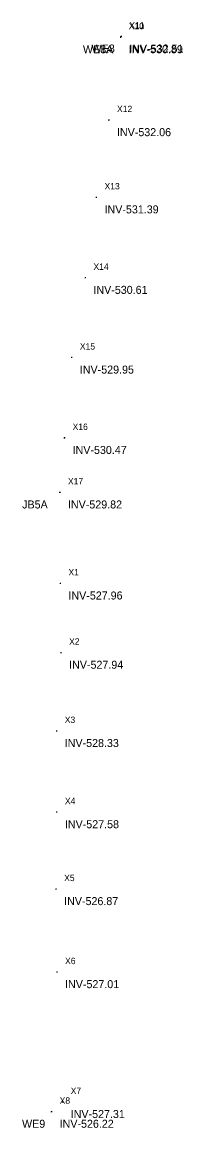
# Model space of a CAD drawing. Extents: x 1725597 to 1725698, y 658797 to 659487.
import ezdxf

# ---------------------------------------------------------------- set-up
doc = ezdxf.new("R2010")
doc.units = 0
for name, color, linetype in [('SURVEY - DRAINAGE - Storm Sewer - Points - Elevations', 7, 'Continuous'), ('SURVEY - DRAINAGE - Storm Sewer - Points - Locators', 7, 'Continuous'), ('SURVEY - DRAINAGE - Storm Sewer - Points - Numbers', 7, 'Continuous'), ('SURVEY - DRAINAGE - Storm Sewer Text', 7, 'Continuous')]:
    doc.layers.add(name, color=color, linetype=linetype)

msp = doc.modelspace()

# ---------------------------------------------------------------- linework, layer by layer
at = {"layer": 'SURVEY - DRAINAGE - Storm Sewer - Points - Locators'}
for p, q in [((1725659.05, 659477.75), (1725658.55, 659477.75)), ((1725658.8, 659477.5), (1725658.8, 659478)), ((1725658.8, 659477.75), (1725658.8, 659477.75)), ((1725658.8, 659477.75), (1725658.8, 659477.75)), ((1725659.43, 659478.22), (1725658.93, 659478.22)), ((1725659.18, 659477.97), (1725659.18, 659478.47)), ((1725659.18, 659478.22), (1725659.18, 659478.22)), ((1725659.18, 659478.22), (1725659.18, 659478.22)), ((1725651.71, 659425.98), (1725651.21, 659425.98)), ((1725651.46, 659425.73), (1725651.46, 659426.23)), ((1725651.46, 659425.98), (1725651.46, 659425.98)), ((1725651.46, 659425.98), (1725651.46, 659425.98)), ((1725643.93, 659377.74), (1725643.43, 659377.74)), ((1725643.68, 659377.49), (1725643.68, 659377.99)), ((1725643.68, 659377.74), (1725643.68, 659377.74)), ((1725643.68, 659377.74), (1725643.68, 659377.74)), ((1725636.99, 659327.47), (1725636.49, 659327.47)), ((1725636.74, 659327.22), (1725636.74, 659327.72)), ((1725636.74, 659327.47), (1725636.74, 659327.47)), ((1725636.74, 659327.47), (1725636.74, 659327.47)), ((1725628.49, 659277.67), (1725627.99, 659277.67)), ((1725628.24, 659277.42), (1725628.24, 659277.92)), ((1725628.24, 659277.67), (1725628.24, 659277.67)), ((1725628.24, 659277.67), (1725628.24, 659277.67)), ((1725623.97, 659227.47), (1725623.47, 659227.47)), ((1725623.72, 659227.22), (1725623.72, 659227.72)), ((1725623.72, 659227.47), (1725623.72, 659227.47)), ((1725623.72, 659227.47), (1725623.72, 659227.47)), ((1725621.06, 659193.43), (1725620.56, 659193.43)), ((1725620.81, 659193.18), (1725620.81, 659193.68)), ((1725620.81, 659193.43), (1725620.81, 659193.43)), ((1725620.81, 659193.43), (1725620.81, 659193.43)), ((1725621.37, 659136.56), (1725620.87, 659136.56)), ((1725621.12, 659136.31), (1725621.12, 659136.81)), ((1725621.12, 659136.56), (1725621.12, 659136.56)), ((1725621.12, 659136.56), (1725621.12, 659136.56)), ((1725621.79, 659093.31), (1725621.29, 659093.31)), ((1725621.54, 659093.06), (1725621.54, 659093.56)), ((1725621.54, 659093.31), (1725621.54, 659093.31)), ((1725621.54, 659093.31), (1725621.54, 659093.31)), ((1725619.06, 659044.41), (1725618.56, 659044.41)), ((1725618.81, 659044.16), (1725618.81, 659044.66)), ((1725618.81, 659044.41), (1725618.81, 659044.41)), ((1725618.81, 659044.41), (1725618.81, 659044.41)), ((1725619.15, 658993.69), (1725618.65, 658993.69)), ((1725618.9, 658993.44), (1725618.9, 658993.94)), ((1725618.9, 658993.69), (1725618.9, 658993.69)), ((1725618.9, 658993.69), (1725618.9, 658993.69)), ((1725618.67, 658945.66), (1725618.17, 658945.66)), ((1725618.42, 658945.41), (1725618.42, 658945.91)), ((1725618.42, 658945.66), (1725618.42, 658945.66)), ((1725618.42, 658945.66), (1725618.42, 658945.66)), ((1725619.26, 658893.8), (1725618.76, 658893.8)), ((1725619.01, 658893.55), (1725619.01, 658894.05)), ((1725619.01, 658893.8), (1725619.01, 658893.8)), ((1725619.01, 658893.8), (1725619.01, 658893.8)), ((1725622.78, 658812.66), (1725622.28, 658812.66)), ((1725622.53, 658812.41), (1725622.53, 658812.91)), ((1725622.53, 658812.66), (1725622.53, 658812.66)), ((1725622.53, 658812.66), (1725622.53, 658812.66)), ((1725615.86, 658806.58), (1725615.36, 658806.58)), ((1725615.61, 658806.33), (1725615.61, 658806.83)), ((1725615.61, 658806.58), (1725615.61, 658806.58)), ((1725615.61, 658806.58), (1725615.61, 658806.58))]:
    msp.add_line(p, q, dxfattribs=at)

# ---------------------------------------------------------------- texts
at = {"layer": 'SURVEY - DRAINAGE - Storm Sewer - Points - Elevations'}
for s, p in [('INV-530.89', (1725663.8, 659467.75)), ('INV-532.51', (1725664.18, 659468.22)), ('INV-532.06', (1725656.46, 659415.98)), ('INV-531.39', (1725648.68, 659367.74)), ('INV-530.61', (1725641.74, 659317.47)), ('INV-529.95', (1725633.24, 659267.67)), ('INV-530.47', (1725628.72, 659217.47)), ('INV-529.82', (1725625.81, 659183.43)), ('INV-527.96', (1725626.12, 659126.56)), ('INV-527.94', (1725626.54, 659083.31)), ('INV-528.33', (1725623.81, 659034.41)), ('INV-527.58', (1725623.9, 658983.69)), ('INV-526.87', (1725623.42, 658935.66)), ('INV-527.01', (1725624.01, 658883.8)), ('INV-527.31', (1725627.53, 658802.66)), ('INV-526.22', (1725620.61, 658796.58))]:
    msp.add_text(s, height=5, dxfattribs=at).set_placement(p)
at = {"layer": 'SURVEY - DRAINAGE - Storm Sewer - Points - Numbers'}
for s, p in [('X10', (1725663.8, 659482.75)), ('X11', (1725664.18, 659483.22)), ('X12', (1725656.46, 659430.98)), ('X13', (1725648.68, 659382.74)), ('X14', (1725641.74, 659332.47)), ('X15', (1725633.24, 659282.67)), ('X16', (1725628.72, 659232.47)), ('X17', (1725625.81, 659198.43)), ('X1', (1725626.12, 659141.56)), ('X2', (1725626.54, 659098.31)), ('X3', (1725623.81, 659049.41)), ('X4', (1725623.9, 658998.69)), ('X5', (1725623.42, 658950.66)), ('X6', (1725624.01, 658898.8)), ('X7', (1725627.53, 658817.66)), ('X8', (1725620.61, 658811.58))]:
    msp.add_text(s, height=4, dxfattribs=at).set_placement(p)
at = {"layer": 'SURVEY - DRAINAGE - Storm Sewer Text'}
for s, p in [('WE8A', (1725635.17, 659467.75)), ('WE8', (1725640.6, 659468.22)), ('JB5A', (1725597.18, 659183.43)), ('WE9', (1725597.11, 658796.58))]:
    msp.add_text(s, height=5, dxfattribs=at).set_placement(p)

doc.saveas('drawing.dxf')
